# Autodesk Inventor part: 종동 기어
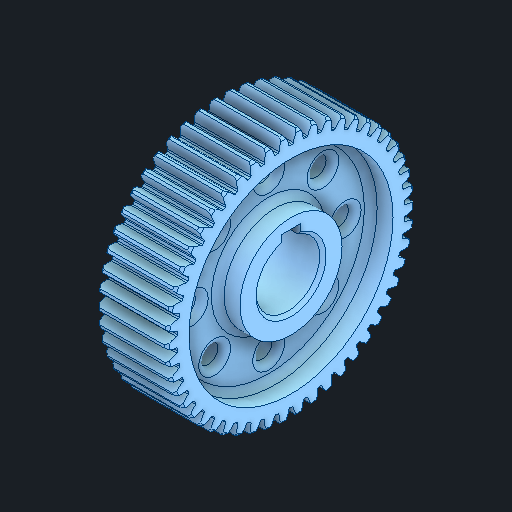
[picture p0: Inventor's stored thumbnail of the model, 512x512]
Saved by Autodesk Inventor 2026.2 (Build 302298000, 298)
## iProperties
Created: 2025-11
Part Number: 종동 기어
Material: 강철, 탄소
Document SubType Name: Modeling
Designer: PC2-07
Density: 7.85 g/cm^3
Appearance: 기본값
Author: jhkim
Sending System: Autodesk Inventor 2026
Preprocessor: ST-DEVELOPER v20.1
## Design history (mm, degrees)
feature "솔리드1"
node "솔리드2"
